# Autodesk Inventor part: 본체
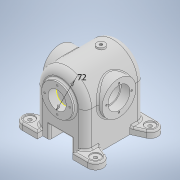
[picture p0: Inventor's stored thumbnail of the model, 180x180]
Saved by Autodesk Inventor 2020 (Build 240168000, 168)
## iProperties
Created: 2024-09
Part Number: 본체
Material: 일반
Document SubType Name: Modeling
Designer: oem
Density: 1 g/cm^3
Appearance: 기본값
Author: oem
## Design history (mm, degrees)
sketch "스케치1"
  geometry: L1 (-45, 0)-(-45, -64); L2 (-45, -64)-(45, -64); L3 (45, -64)-(45, 0); A1 r 45 centre (0, 0) between (45, 0) and (-45, 0); 1 further point
  constraints: 6 end point, 2 point on circle, 1 centre point, 1 coincident, 1 perpendicular, 1 tangent, 1 vertical
  dimensions: "d0" = 90 diameter of A1; "d1" = 64 distance from line of L2 point (0, 0); "d2" = 64 distance of L2.end L3.end; "d3" = 64 distance of L1.start L1.end
extrude "돌출1" new body sketch "스케치1" stored distance "d4" = 108; taper "d5" = 0 deg
sketch "스케치4"
  geometry: C1 r 28.5 at (0, 0); A1 r 45 centre (0, 0) between (45, 0) and (-45, 0) reference
  constraints: 1 centre point, 1 coincident
  dimensions: "d6" = 57 diameter of C1
extrude "돌출2" join sketch "스케치4" distance "d7" = 6; taper "d8" = 0 deg
sketch "스케치5"
  geometry: C1 r 28.5 at (0, 0) reference; C2 r 16.5 at (0, 0)
  constraints: 1 centre point, 1 coincident
  dimensions: "d9" = 33 diameter of C2
extrude "돌출3" cut sketch "스케치5" distance "d10" = 1; taper "d11" = 0 deg
node "작업 평면1"
sketch "스케치8"
  geometry: L1 (119, 10)-(-29, 10); L2 (-29, 10)-(-29, -118); L3 (-29, -118)-(119, -118); L4 (119, -118)-(119, 10); L5 (119, -118)-(-29, 10); L6 (119, 10)-(-29, -118); 2 further points
  constraints: 12 end point, 2 parallel, 1 coincident, 1 horizontal, 1 midpoint, 1 perpendicular
  dimensions: "d27" = 128 distance of L1.end L2.end; "d28" = 148 distance of L2.end L3.end
extrude "돌출5" join sketch "스케치8" distance "d29" = 12; taper "d30" = 0 deg
sketch "스케치9"
  geometry: L1 (148, -12)-(0, -12) reference; L2 (54, 11)-(94, 11); L3 (94, 11)-(94, -12); L4 (94, -12)-(54, -12); L5 (54, -12)-(54, 11); 3 further points
  constraints: 8 end point, 2 parallel, 1 horizontal, 1 midpoint, 1 perpendicular, 1 point on line, 1 vertical alignment
  dimensions: "d31" = 40 distance between parallel lines of L3 L5; "d32" = 23 distance between parallel lines of L1 L2
extrude "돌출6" cut sketch "스케치9" extent not by distance; stored distance "d33" = 0; taper "d34" = 0 deg
sketch "스케치13"
  geometry: L1 (65, 0)-(65, -10) reference; L2 (119, -10)-(65, -10) reference; L3 (119, 118)-(119, -10) reference; L4 (65, 118)-(119, 118) reference; L5 (65, 118)-(65, 108) reference; L6 (90, 108)-(65, 108) reference; L7 (90, 108)-(90, 0) reference; L8 (65, 0)-(90, 0) reference; 1 further point
fillet "모깎기3" dims "d35" = 3
sketch "스케치14"
  geometry: L1 (65, 0)-(65, -10) reference; L2 (119, -10)-(65, -10) reference; L3 (119, 118)-(119, -10) reference; L4 (65, 118)-(119, 118) reference; L5 (65, 118)-(65, 108) reference; L6 (90, 108)-(65, 108) reference; L7 (90, 108)-(90, 0) reference; L8 (65, 0)-(90, 0) reference; L9 (-29, 118)-(25, 118) reference; L10 (110.693, 91.21)-(90, 82); L11 (90, 108)-(90, 0) reference; L12 (72, 118)-(72, 108); L13 (110.693, 16.79)-(90, 26); L14 (77.5, 0)-(77.5, -10); L15 (105, 118)-(72, 118); L16 (105, -10)-(77.5, -10); L17 (-20.693, 16.79)-(0, 26); L18 (0, 108)-(0, 0) reference; L19 (0, 0)-(25, 0) reference; L20 (18, 0)-(18, -10); L21 (25, -10)-(-29, -10) reference; L22 (-20.693, 91.21)-(0, 82); L23 (90, 108)-(0, 108) reference; L24 (18, 108)-(18, 118); L25 (-15, -10)-(18, -10); L26 (-15, 118)-(18, 118); A1 r 14 centre (105, 104) between (110.693, 91.21) and (105, 118); A2 r 14 centre (105, 4) between (105, -10) and (110.693, 16.79); A3 r 14 centre (-15, 4) between (-20.693, 16.79) and (-15, -10); A4 r 14 centre (-15, 104) between (-20.693, 91.21) and (-15, 118); 9 further points
  constraints: 24 end point, 15 point on line, 8 point on circle, 4 centre point, 4 coincident, 4 tangent, 3 perpendicular, 3 vertical, 2 collinear, 1 midpoint
  dimensions: "d36" = 14 distance from line of point (105, 104) L4; "d37" = 100 distance of point (105, 104) point (105, 4); "d38" = 120 distance of point (105, 104) point (-15, 104); "d39" = 100 distance of point (-15, 4) point (-15, 104); "d40" = 120 distance of point (105, 4) point (-15, 4); "d41" = 14 distance from line of point (105, 4) L2; "d42" = 14 distance from line of L9 point (-15, 104); "d43" = 14 distance from line of L3 point (105, 104); "d44" = 28 diameter of A1; "d45" = 36 distance from line of L10.end L4; "d46" = 18 distance between parallel lines of L11 L12; "d47" = 28 diameter of A2; "d48" = 36 distance from line of L2 L13.end; "d49" = 28 diameter of A3; "d50" = 28 diameter of A4; "d51" = 18 distance between parallel lines of L24 L18; "d52" = 18 distance between parallel lines of L18 L20; "d53" = 36 distance from line of L9 L22.end; "d54" = 36 distance from line of L21 L17.end
extrude "돌출7" cut sketch "스케치14" distance "d55" = 12; taper "d56" = 0 deg
node "작업 평면2"
hole "구멍2" sketch "스케치14" diameter "d57" = 6.6; stored, may be unused: countersink angle "d61" = 90 deg, drill point angle "d63" = 118 deg; dims "d58" = 8, "d59" = 4, "d60" = 2, "d62" = 10
sketch "스케치17"
  geometry: C1 r 3.3 at (-15, 4) reference; C2 r 3.3 at (-15, 4) reference; C3 r 9 at (-15, 4); 1 further point
  constraints: 1 centre point, 1 coincident
  dimensions: "d64" = 18 diameter of C3
extrude "돌출8" cut sketch "스케치17" distance "d65" = 2; taper "d66" = 0 deg
sketch "스케치18"
  geometry: C1 r 3.3 at (-15, 104) reference; C2 r 9 at (-15, 104); C3 r 3.3 at (105, 104) reference; C4 r 9 at (105, 104); C5 r 3.3 at (105, 4) reference; C6 r 9 at (105, 4); A1 r 14 centre (-15, 104) between (-15, 118) and (-20.693, 91.21) reference; 1 further point
  constraints: 3 centre point, 3 coincident
  dimensions: "d67" = 18 diameter of C2; "d68" = 18 diameter of C4; "d70" = 18 diameter of C6
extrude "돌출9" cut sketch "스케치18" distance "d71" = 2; taper "d72" = 0 deg
node "작업 평면3"
sketch "스케치19"
  geometry: C1 r 31 at (54, 0); 1 further point
  constraints: 1 centre point, 1 coincident
  dimensions: "d74" = 62 diameter of C1
extrude "돌출10" join sketch "스케치19" distance "d75" = 108; taper "d76" = 0 deg
sketch "스케치20"
  geometry: C1 r 31 at (0, 0) reference; C2 r 20 at (0, 0)
  constraints: 1 centre point, 1 coincident
  dimensions: "d77" = 40 diameter of C2
extrude "돌출11" cut sketch "스케치20" distance "d78" = 16; taper "d79" = 0 deg
sketch "스케치21"
  geometry: C1 r 20 at (0, 0) reference; C2 r 17.5 at (0, 0)
  constraints: 1 centre point, 1 coincident
  dimensions: "d80" = 35 diameter of C2
extrude "돌출12" cut sketch "스케치21" extent not by distance; stored distance "d81" = 16; taper "d82" = 0 deg
sketch "스케치22"
  geometry: C1 r 20 at (0, 0) reference; 1 further point
  constraints: 1 vertical alignment
  dimensions: "d83" = 23 distance of point (0, 23) C1.centre
hole "구멍3" sketch "스케치22" at (0, 23) diameter "d84" = 3.242; stored, may be unused: countersink angle "d88" = 90 deg, drill point angle "d90" = 118 deg; dims "d85" = 8, "d86" = 4, "d87" = 2, "d89" = 10
node "작업 평면5"
sketch "스케치23"
  geometry: C1 r 16.5 at (0, 0) reference; 1 further point
  constraints: 1 vertical alignment
  dimensions: "d94" = 23 distance of point (0, 23) C1.centre
hole "구멍4" sketch "스케치23" at (0, 23) diameter "d95" = 3.242; stored, may be unused: countersink angle "d99" = 90 deg, drill point angle "d101" = 118 deg; dims "d96" = 8, "d97" = 4, "d98" = 2, "d100" = 10
fillet "모깎기4" dims "d105" = 12
fillet "모깎기5" dims "d106" = 3
fillet "모깎기6" dims "d107" = 3
node "작업 평면7"
sketch "스케치26"
  geometry: L1 (-33, 54)-(33, 54) reference; C1 r 7.5 at (0, -20); 1 further point
  constraints: 1 centre point, 1 vertical alignment
  dimensions: "d108" = 15 diameter of C1; "d109" = 74 distance from line of L1 C1.centre
extrude "돌출13" join sketch "스케치26" stored distance "d110" = 6; taper "d111" = 0 deg
sketch "스케치29"
  geometry: C1 r 16.5 at (0, 0) reference; C2 r 28.5 at (0, 0) reference; C3 r 16.5 at (0, 0)
  constraints: 1 centre point, 1 coincident
  dimensions: "d112" = 33 diameter of C3
extrude "돌출14" cut sketch "스케치29" distance "d113" = 15; taper "d114" = 0 deg
sketch "스케치30"
  geometry: C1 r 7.5 at (0, 0) reference; 2 further points
  constraints: 1 coincident
hole "구멍5" sketch "스케치30" at (0, 0) diameter "d115" = 5.1881; stored, may be unused: countersink angle "d119" = 90 deg, drill point angle "d121" = 118 deg; dims "d116" = 12, "d117" = 4, "d118" = 2, "d120" = 16
sketch "스케치31"
  geometry: 1 further point
sketch "스케치32"
  geometry: C1 r 16.5 at (0, 0) reference; C2 r 36 at (0, 0)
  constraints: 1 centre point, 1 coincident
  dimensions: "d122" = 72 diameter of C2
node "솔리드1"
mirror "미러1"
pattern_circular "원형 패턴1" dims angle "d92" = 360 deg
mirror "미러3"
pattern_circular "원형 패턴2" dims angle "d103" = 360 deg
feature "A9D066F2-1C7D-4E18-AEED-F7BC21143FA4" dims "d57" = 6.6, "d58" = 8, "d59" = 4, "d60" = 2, "d61" = 90 deg, "d62" = 10, "d63" = 118 deg
other parameters: "d14" = -125, "d73" = 8
